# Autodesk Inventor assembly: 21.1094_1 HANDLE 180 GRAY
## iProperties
Created: 2007-03
Part Number: 21.1094_1 HANDLE 180 GRAY
Document SubType Name: Assembly
Designer: Andy Moles
Mass: 90.8015 g
Surface Area: 233.961 cm^2
Volume: 59.129 cm^3
Density: 1.53565 g/cm^3
Author: Andy Moles
